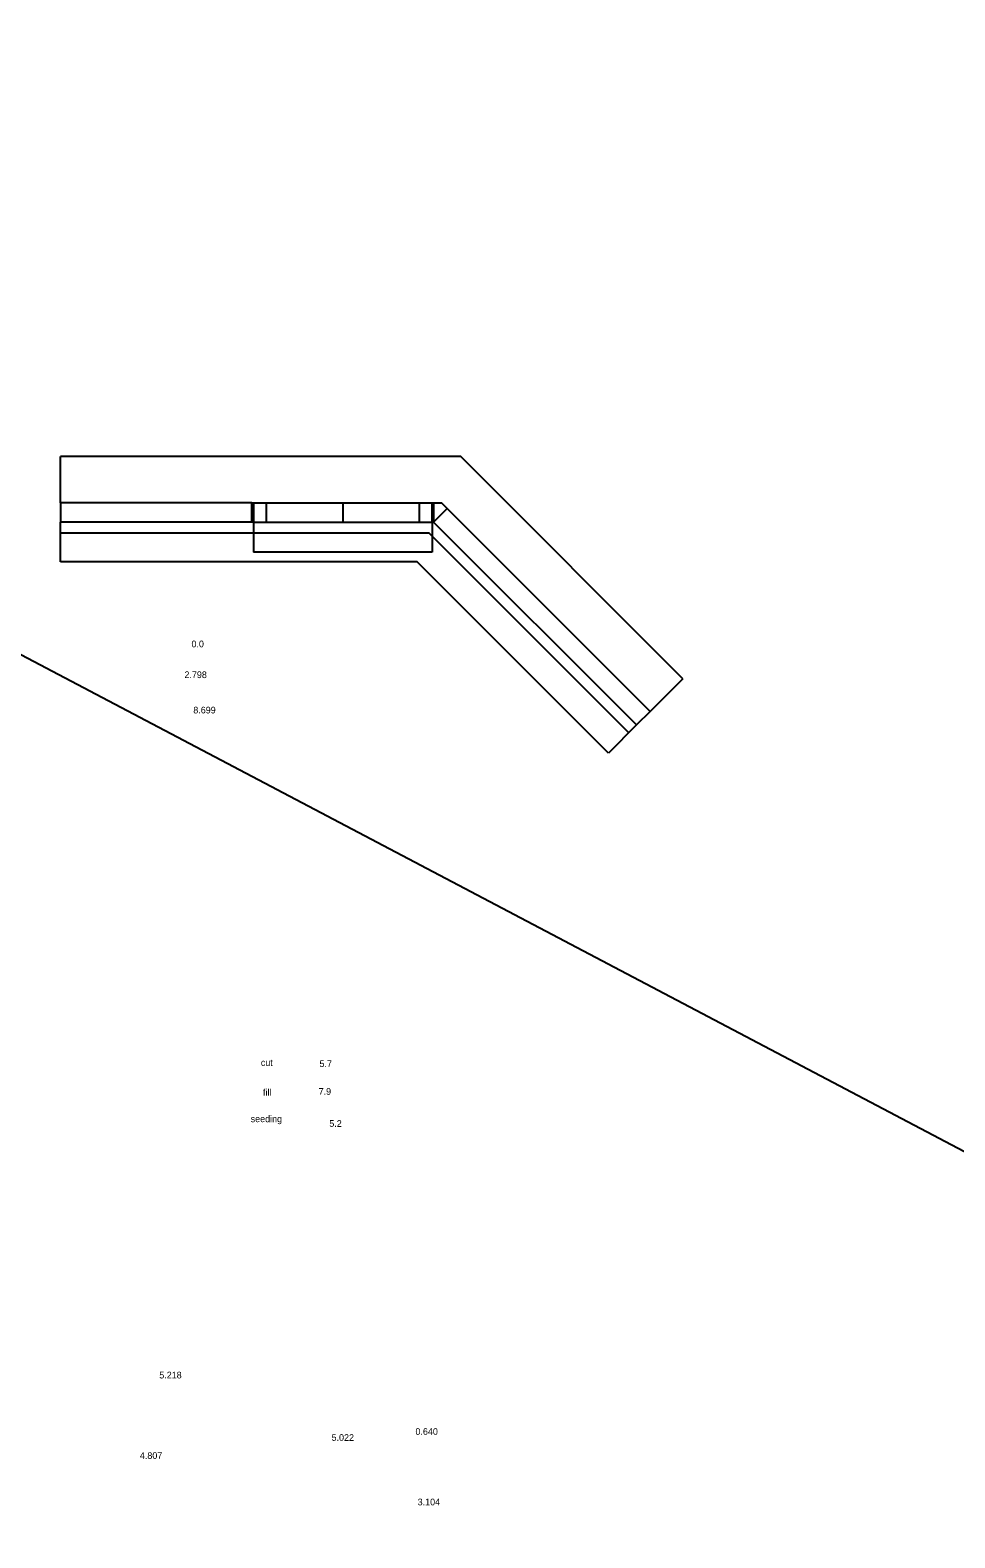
# Model space of a CAD drawing. Extents: x -70 to 515, y 642 to 823.
# Drawn here: x 249.7 to 298, y 744.2 to 823 of the extents above; entities that cross this region are included whole.
import ezdxf

# ---------------------------------------------------------------- set-up
doc = ezdxf.new("R2010")
doc.units = 0
for name, color, linetype in [('DR_P_Culvert', 7, 'Continuous'), ('DR_P_Headwall', 7, 'Continuous'), ('DT_X_Terrain_Boundary', 7, 'Continuous'), ('DT_X_Void', 7, 'Continuous'), ('XS_P_Finished_Grade', 7, 'Continuous')]:
    doc.layers.add(name, color=color, linetype=linetype)

msp = doc.modelspace()

# ---------------------------------------------------------------- linework, layer by layer
at = {"layer": 'DR_P_Culvert'}
for p, q in [((262.01, 798.303), (262.01, 797.303)), ((266.01, 798.303), (266.01, 797.303)), ((270.01, 798.303), (270.01, 797.303))]:
    msp.add_line(p, q, dxfattribs=at)
at = {"layer": 'DR_P_Headwall'}
for p, q in [((261.343, 800.72), (251.26, 800.72)), ((251.26, 798.303), (251.26, 800.72)), ((270.677, 800.72), (261.343, 800.72)), ((272.175, 800.72), (270.677, 800.72)), ((283.783, 789.113), (272.175, 800.72)), ((261.26, 798.303), (251.26, 798.303)), ((251.26, 798.303), (251.26, 797.303)), ((261.343, 798.303), (270.677, 798.303)), ((270.76, 798.303), (271.174, 798.303)), ((270.76, 797.303), (271.467, 798.01)), ((282.074, 787.404), (271.174, 798.303)), ((251.26, 795.22), (251.26, 797.303)), ((261.26, 797.303), (251.26, 797.303)), ((261.343, 797.303), (261.343, 795.72)), ((261.343, 797.303), (270.677, 797.303)), ((270.677, 797.303), (270.677, 795.72)), ((281.367, 786.697), (270.76, 797.303)), ((270.518, 796.72), (251.26, 796.72)), ((280.954, 786.284), (270.518, 796.72)), ((270.677, 795.72), (261.343, 795.72)), ((269.897, 795.22), (251.26, 795.22)), ((279.894, 785.223), (269.897, 795.22)), ((283.783, 789.113), (282.074, 787.404)), ((282.074, 787.404), (281.367, 786.697)), ((281.367, 786.697), (279.894, 785.223))]:
    msp.add_line(p, q, dxfattribs=at)
at = {"layer": 'DT_X_Void'}
for points in [[(261.343, 798.303), (261.343, 797.303), (261.26, 797.303), (261.26, 798.303)], [(270.76, 798.303), (270.76, 797.303), (270.677, 797.303), (270.677, 798.303)]]:
    msp.add_lwpolyline(points, close=True, dxfattribs=at)
at = {"layer": 'XS_P_Finished_Grade'}
msp.add_line((187.231, 823.016), (511.019, 652.405), dxfattribs=at)

# ---------------------------------------------------------------- texts
at = {"layer": 'DT_X_Terrain_Boundary'}
for s, p in [('0.0', (258.101, 790.755)), ('2.798', (257.733, 789.143)), ('8.699', (258.196, 787.295)), ('cut', (261.727, 768.867)), ('5.7', (264.793, 768.81)), ('7.9', (264.749, 767.358)), ('fill', (261.838, 767.314)), ('seeding', (261.196, 765.927)), ('5.2', (265.306, 765.683)), ('5.218', (256.418, 752.531)), ('5.022', (265.424, 749.267)), ('4.807 ', (255.404, 748.323)), ('3.104', (269.924, 745.897))]:
    msp.add_text(s, height=0.35, dxfattribs=at).set_placement(p)
at = {"layer": 'XS_P_Finished_Grade'}
msp.add_text('0.640', height=0.35, dxfattribs=at).set_placement((269.809, 749.582))

doc.saveas('drawing.dxf')
